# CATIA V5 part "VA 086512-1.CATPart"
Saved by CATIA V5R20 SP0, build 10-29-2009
Part number: VA 086512-1
Revision: ANY
Definition: UNKNOWN
Nomenclature: VA 086512-1
Source: Unknown
Bounding box of the stored display mesh (mm): x -3.305 to 3.305, y 0 to 10.6, z -3.143 to 3.143
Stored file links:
  C:\Users\Utente\Desktop\IO LAVORO\3D X SITO CF\CUMSA\3D files VA\VA 086512\VA 086512-1.CATPart
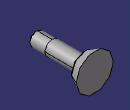
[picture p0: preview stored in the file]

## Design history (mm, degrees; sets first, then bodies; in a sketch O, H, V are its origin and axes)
Body1 "Cortar-Extruir2" (main body)
  Solid1: solid without history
